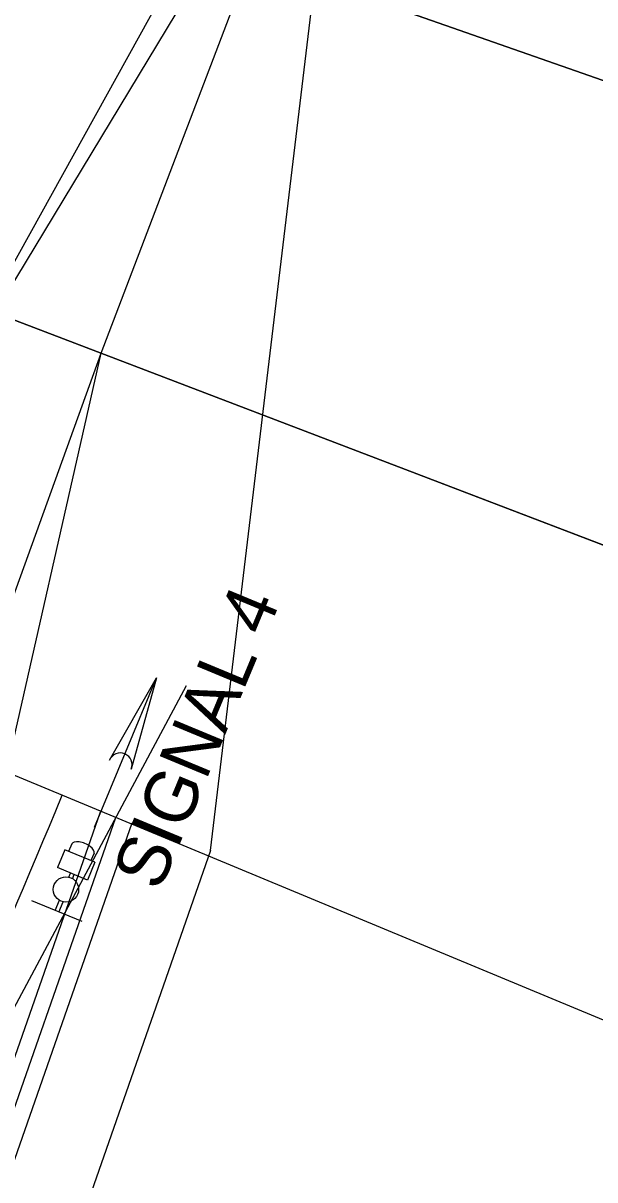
# Model space of a CAD drawing. Extents: x 2034057 to 2035954, y 247386 to 249135.
# Drawn here: x 2034295.3 to 2034329.5, y 247905.2 to 247974.4 of the extents above; entities that cross this region are included whole.
import ezdxf

# ---------------------------------------------------------------- set-up
doc = ezdxf.new("R2010")
doc.units = 0
for name, color, linetype in [('Default', 7, 'Continuous'), ('DR_X_Storm_Sewer', 7, 'Continuous'), ('DR_X_Text', 7, 'Continuous'), ('PV_X_Driveway', 7, 'Continuous'), ('RD_X_GR_Lt', 7, 'Continuous'), ('RD_X_GR_Rt', 7, 'Continuous'), ('RS_Raster1', 7, 'Continuous'), ('RW_X_CL', 7, 'Continuous'), ('SC_Scratch1', 7, 'Continuous'), ('SV_X_Break_Lines', 7, 'Continuous'), ('XS_X_Ground_Line', 7, 'Continuous')]:
    doc.layers.add(name, color=color, linetype=linetype)

msp = doc.modelspace()

# ---------------------------------------------------------------- linework, layer by layer
at = {"layer": 'Default'}
for p, q in [((2034204.499, 248014.816), (2034393.285, 247948.789)), ((2034196.894, 247994.035), (2034383.708, 247922.617)), ((2034188.696, 247973.481), (2034373.384, 247896.73))]:
    msp.add_line(p, q, dxfattribs=at)
at = {"layer": 'DR_X_Storm_Sewer'}
for points in [[(2034299.922, 247927.196), (2034291.463, 247902.991), (2034279.823, 247880.164)], [(2034301.81, 247926.537), (2034293.307, 247902.203), (2034281.623, 247879.292)]]:
    msp.add_lwpolyline(points, dxfattribs=at)
msp.add_arc((2033476.727, 248269.353), 889, 333.312654, 337.433726, dxfattribs=at)
at = {"layer": 'DR_X_Text'}
msp.add_lwpolyline([(2034271.109, 247872.326), (2034288.746, 247904.233), (2034305.089, 247934.751)], dxfattribs=at)
at = {"layer": 'PV_X_Driveway'}
msp.add_line((2034268.836, 247913.186), (2034315.331, 247997.175), dxfattribs=at)
at = {"layer": 'RD_X_GR_Lt'}
msp.add_line((2034293.515, 247926.057), (2034299.984, 247954.624), dxfattribs=at)
msp.add_lwpolyline([(2034299.984, 247954.624), (2034308.713, 247977.534), (2034315.331, 247997.175)], dxfattribs=at)
at = {"layer": 'RD_X_GR_Rt'}
for p, q in [((2034299.587, 247926.299), (2034303.292, 247935.218)), ((2034300.486, 247930.293), (2034303.292, 247935.218)), ((2034303.292, 247935.218), (2034301.783, 247929.754)), ((2034298.23, 247925.288), (2034298.045, 247924.841)), ((2034298.23, 247925.288), (2034298.045, 247924.841)), ((2034297.812, 247924.931), (2034297.374, 247923.872)), ((2034299.606, 247924.189), (2034297.812, 247924.931)), ((2034299.562, 247924.737), (2034299.377, 247924.29)), ((2034299.562, 247924.737), (2034299.377, 247924.29)), ((2034299.167, 247923.13), (2034297.374, 247923.872)), ((2034299.606, 247924.189), (2034299.167, 247923.13)), ((2034298.058, 247923.301), (2034298.16, 247923.546)), ((2034298.058, 247923.301), (2034298.16, 247923.546)), ((2034298.28, 247923.21), (2034298.381, 247923.455)), ((2034298.28, 247923.21), (2034298.381, 247923.455)), ((2034298.844, 247920.643), (2034295.85, 247921.881)), ((2034297.236, 247921.308), (2034297.488, 247921.919)), ((2034297.236, 247921.308), (2034297.488, 247921.919)), ((2034297.458, 247921.216), (2034297.71, 247921.828)), ((2034297.458, 247921.216), (2034297.71, 247921.828))]:
    msp.add_line(p, q, dxfattribs=at)
msp.add_circle((2034297.884, 247922.565), 0.757, dxfattribs=at)
msp.add_arc((2034301.134, 247930.023), 0.702, 337.44303, 157.44303, dxfattribs=at)
msp.add_ellipse((2034298.896, 247925.012), major_axis=(0.666, -0.275), ratio=0.45371, start_param=0, end_param=3.141593, dxfattribs=at)
msp.add_ellipse((2034298.896, 247925.012), major_axis=(0.666, -0.275), ratio=0.45371, start_param=0, end_param=3.141593, dxfattribs=at)
at = {"layer": 'RS_Raster1'}
msp.add_line((2034256.557, 247895.646), (2034312.078, 247987.523), dxfattribs=at)
at = {"layer": 'RW_X_CL'}
for points in [[(2034204.499, 248014.816), (2034393.285, 247948.789), (2034393.285, 247948.789), (2034204.499, 248014.816)], [(2034196.894, 247994.035), (2034383.708, 247922.617), (2034383.708, 247922.617), (2034196.894, 247994.035)]]:
    msp.add_lwpolyline(points, close=True, dxfattribs=at)
at = {"layer": 'SC_Scratch1'}
msp.add_line((2034292.934, 247935.094), (2034299.984, 247954.624), dxfattribs=at)
at = {"layer": 'SV_X_Break_Lines'}
msp.add_lwpolyline([(2034273.172, 247864.921), (2034292.385, 247902.597), (2034300.866, 247926.866)], dxfattribs=at)
at = {"layer": 'XS_X_Ground_Line'}
for points in [[(2034306.53, 247924.887), (2034312.657, 247976.067), (2034320.778, 248001.075), (2034292.961, 248009.917)], [(2034306.53, 247924.887), (2034297.915, 247900.234), (2034286.009, 247876.887), (2034278.747, 247864.538), (2034281.434, 247858.085), (2034292.434, 247848.028)]]:
    msp.add_lwpolyline(points, dxfattribs=at)

# ---------------------------------------------------------------- texts
at = {"layer": 'RD_X_GR_Rt'}
msp.add_text('SIGNAL 4', height=3.125, rotation=67.44303, dxfattribs=at).set_placement((2034303.481, 247922.375))

doc.saveas('drawing.dxf')
